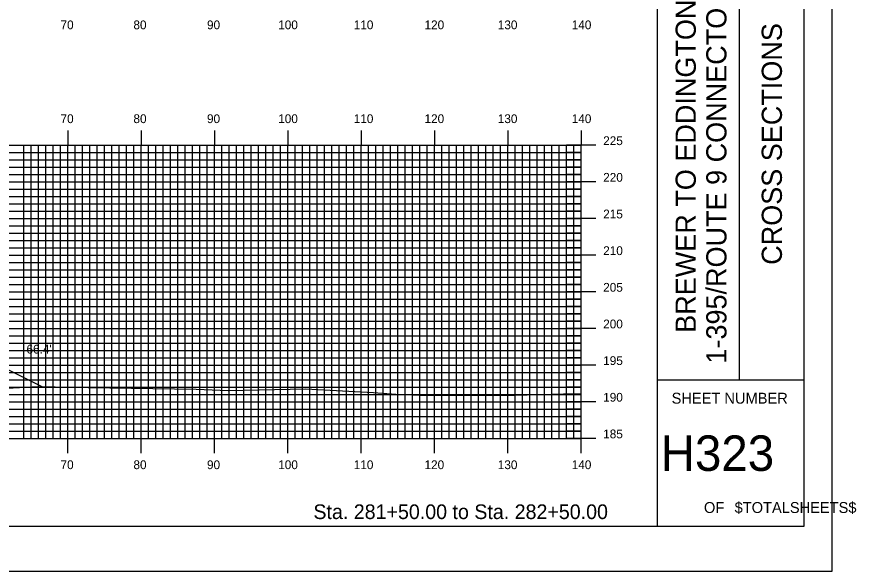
# Model space of a CAD drawing. Extents: x 1811374 to 1811717, y 442591 to 442811.
# Drawn here: x 1811602.4 to 1811716.9, y 442590.5 to 442666.2 of the extents above; entities that cross this region are included whole.
import ezdxf

# ---------------------------------------------------------------- set-up
doc = ezdxf.new("R2010")
doc.units = 0
for name, color, linetype in [('BORDER', 7, 'Continuous'), ('D_Roadway_Centerline', 7, 'Continuous'), ('D_Roadway_SlopeLines', 7, 'Continuous'), ('D_Text_Standard', 7, 'Continuous'), ('H_V ANNOTATION', 7, 'Continuous'), ('MAJOR', 7, 'Continuous'), ('MINOR', 7, 'Continuous'), ('PLOT BOUNDARY', 7, 'Continuous'), ('S_Roadway_Centerline', 7, 'Continuous')]:
    doc.layers.add(name, color=color, linetype=linetype)

msp = doc.modelspace()

# ---------------------------------------------------------------- linework, layer by layer
at = {"layer": 'BORDER'}
for p, q in [((1811689.8, 442596.67), (1811689.8, 442806.67)), ((1811700.98, 442616.67), (1811700.98, 442686.67)), ((1811689.8, 442616.67), (1811709.8, 442616.67))]:
    msp.add_line(p, q, dxfattribs=at)
msp.add_lwpolyline([(1811389.8, 442596.67), (1811709.8, 442596.67), (1811709.8, 442806.67), (1811389.8, 442806.67)], close=True, dxfattribs=at)
at = {"layer": 'D_Roadway_Centerline'}
msp.add_lwpolyline([(1811469.9, 442615.65), (1811511.19, 442636.3), (1811516.4, 442638.9), (1811519.4, 442638.96), (1811527.4, 442639.12), (1811539.4, 442638.54), (1811551.4, 442637.97), (1811559.4, 442637.58), (1811562.4, 442637.44), (1811567.93, 442634.68), (1811605.84, 442615.72)], dxfattribs=at)
at = {"layer": 'D_Roadway_SlopeLines'}
msp.add_lwpolyline([(1811562.4, 442637.44), (1811605.84, 442615.72)], dxfattribs=at)
at = {"layer": 'MAJOR'}
for p, q in [((1811609.4, 442650.67), (1811609.4, 442648.67)), ((1811619.4, 442650.67), (1811619.4, 442648.67)), ((1811629.4, 442650.67), (1811629.4, 442648.67)), ((1811639.4, 442650.67), (1811639.4, 442648.67)), ((1811649.4, 442650.67), (1811649.4, 442648.67)), ((1811659.4, 442650.67), (1811659.4, 442648.67)), ((1811669.4, 442650.67), (1811669.4, 442648.67)), ((1811679.4, 442650.67), (1811679.4, 442648.67)), ((1811399.4, 442648.67), (1811679.4, 442648.67)), ((1811399.4, 442648.67), (1811679.4, 442648.67)), ((1811609.4, 442608.67), (1811609.4, 442648.67)), ((1811619.4, 442608.67), (1811619.4, 442648.67)), ((1811629.4, 442608.67), (1811629.4, 442648.67)), ((1811639.4, 442608.67), (1811639.4, 442648.67)), ((1811649.4, 442608.67), (1811649.4, 442648.67)), ((1811659.4, 442608.67), (1811659.4, 442648.67)), ((1811669.4, 442608.67), (1811669.4, 442648.67)), ((1811681.41, 442648.67), (1811677.4, 442648.67)), ((1811679.4, 442608.67), (1811679.4, 442648.67)), ((1811679.4, 442608.67), (1811679.4, 442648.67)), ((1811399.4, 442643.67), (1811679.4, 442643.67)), ((1811681.41, 442643.67), (1811677.4, 442643.67)), ((1811399.4, 442638.67), (1811679.4, 442638.67)), ((1811681.41, 442638.67), (1811677.4, 442638.67)), ((1811399.4, 442633.67), (1811679.4, 442633.67)), ((1811681.41, 442633.67), (1811677.4, 442633.67)), ((1811399.4, 442628.67), (1811679.4, 442628.67)), ((1811681.41, 442628.67), (1811677.4, 442628.67)), ((1811399.4, 442623.67), (1811679.4, 442623.67)), ((1811681.41, 442623.67), (1811677.4, 442623.67)), ((1811399.4, 442618.67), (1811679.4, 442618.67)), ((1811681.41, 442618.67), (1811677.4, 442618.67)), ((1811399.4, 442613.67), (1811679.4, 442613.67)), ((1811681.41, 442613.67), (1811677.4, 442613.67)), ((1811399.4, 442608.67), (1811679.4, 442608.67)), ((1811399.4, 442608.67), (1811679.4, 442608.67)), ((1811609.4, 442606.66), (1811609.4, 442608.67)), ((1811619.4, 442606.66), (1811619.4, 442608.67)), ((1811629.4, 442606.66), (1811629.4, 442608.67)), ((1811639.4, 442606.66), (1811639.4, 442608.67)), ((1811649.4, 442606.66), (1811649.4, 442608.67)), ((1811659.4, 442606.66), (1811659.4, 442608.67)), ((1811669.4, 442606.66), (1811669.4, 442608.67)), ((1811681.41, 442608.67), (1811677.4, 442608.67)), ((1811679.4, 442606.66), (1811679.4, 442608.67))]:
    msp.add_line(p, q, dxfattribs=at)
at = {"layer": 'MINOR'}
for p, q in [((1811603.4, 442608.67), (1811603.4, 442648.67)), ((1811604.4, 442608.67), (1811604.4, 442648.67)), ((1811605.4, 442608.67), (1811605.4, 442648.67)), ((1811606.4, 442608.67), (1811606.4, 442648.67)), ((1811607.4, 442608.67), (1811607.4, 442648.67)), ((1811608.4, 442608.67), (1811608.4, 442648.67)), ((1811610.4, 442608.67), (1811610.4, 442648.67)), ((1811611.4, 442608.67), (1811611.4, 442648.67)), ((1811612.4, 442608.67), (1811612.4, 442648.67)), ((1811613.4, 442608.67), (1811613.4, 442648.67)), ((1811614.4, 442608.67), (1811614.4, 442648.67)), ((1811615.4, 442608.67), (1811615.4, 442648.67)), ((1811616.4, 442608.67), (1811616.4, 442648.67)), ((1811617.4, 442608.67), (1811617.4, 442648.67)), ((1811618.4, 442608.67), (1811618.4, 442648.67)), ((1811620.4, 442608.67), (1811620.4, 442648.67)), ((1811621.4, 442608.67), (1811621.4, 442648.67)), ((1811622.4, 442608.67), (1811622.4, 442648.67)), ((1811623.4, 442608.67), (1811623.4, 442648.67)), ((1811624.4, 442608.67), (1811624.4, 442648.67)), ((1811625.4, 442608.67), (1811625.4, 442648.67)), ((1811626.4, 442608.67), (1811626.4, 442648.67)), ((1811627.4, 442608.67), (1811627.4, 442648.67)), ((1811628.4, 442608.67), (1811628.4, 442648.67)), ((1811630.4, 442608.67), (1811630.4, 442648.67)), ((1811631.4, 442608.67), (1811631.4, 442648.67)), ((1811632.4, 442608.67), (1811632.4, 442648.67)), ((1811633.4, 442608.67), (1811633.4, 442648.67)), ((1811634.4, 442608.67), (1811634.4, 442648.67)), ((1811635.4, 442608.67), (1811635.4, 442648.67)), ((1811636.4, 442608.67), (1811636.4, 442648.67)), ((1811637.4, 442608.67), (1811637.4, 442648.67)), ((1811638.4, 442608.67), (1811638.4, 442648.67)), ((1811640.4, 442608.67), (1811640.4, 442648.67)), ((1811641.4, 442608.67), (1811641.4, 442648.67)), ((1811642.4, 442608.67), (1811642.4, 442648.67)), ((1811643.4, 442608.67), (1811643.4, 442648.67)), ((1811644.4, 442608.67), (1811644.4, 442648.67)), ((1811645.4, 442608.67), (1811645.4, 442648.67)), ((1811646.4, 442608.67), (1811646.4, 442648.67)), ((1811647.4, 442608.67), (1811647.4, 442648.67)), ((1811648.4, 442608.67), (1811648.4, 442648.67)), ((1811650.4, 442608.67), (1811650.4, 442648.67)), ((1811651.4, 442608.67), (1811651.4, 442648.67)), ((1811652.4, 442608.67), (1811652.4, 442648.67)), ((1811653.4, 442608.67), (1811653.4, 442648.67)), ((1811654.4, 442608.67), (1811654.4, 442648.67)), ((1811655.4, 442608.67), (1811655.4, 442648.67)), ((1811656.4, 442608.67), (1811656.4, 442648.67)), ((1811657.4, 442608.67), (1811657.4, 442648.67)), ((1811658.4, 442608.67), (1811658.4, 442648.67)), ((1811660.4, 442608.67), (1811660.4, 442648.67)), ((1811661.4, 442608.67), (1811661.4, 442648.67)), ((1811662.4, 442608.67), (1811662.4, 442648.67)), ((1811663.4, 442608.67), (1811663.4, 442648.67)), ((1811664.4, 442608.67), (1811664.4, 442648.67)), ((1811665.4, 442608.67), (1811665.4, 442648.67)), ((1811666.4, 442608.67), (1811666.4, 442648.67)), ((1811667.4, 442608.67), (1811667.4, 442648.67)), ((1811668.4, 442608.67), (1811668.4, 442648.67)), ((1811670.4, 442608.67), (1811670.4, 442648.67)), ((1811671.4, 442608.67), (1811671.4, 442648.67)), ((1811672.4, 442608.67), (1811672.4, 442648.67)), ((1811673.4, 442608.67), (1811673.4, 442648.67)), ((1811674.4, 442608.67), (1811674.4, 442648.67)), ((1811675.4, 442608.67), (1811675.4, 442648.67)), ((1811676.4, 442608.67), (1811676.4, 442648.67)), ((1811677.4, 442608.67), (1811677.4, 442648.67)), ((1811678.4, 442608.67), (1811678.4, 442648.67)), ((1811399.4, 442647.67), (1811679.4, 442647.67)), ((1811399.4, 442646.67), (1811679.4, 442646.67)), ((1811679.4, 442647.67), (1811677.4, 442647.67)), ((1811679.4, 442646.67), (1811677.4, 442646.67)), ((1811399.4, 442645.67), (1811679.4, 442645.67)), ((1811679.4, 442645.67), (1811677.4, 442645.67)), ((1811399.4, 442644.67), (1811679.4, 442644.67)), ((1811679.4, 442644.67), (1811677.4, 442644.67)), ((1811399.4, 442642.67), (1811679.4, 442642.67)), ((1811679.4, 442642.67), (1811677.4, 442642.67)), ((1811399.4, 442641.67), (1811679.4, 442641.67)), ((1811679.4, 442641.67), (1811677.4, 442641.67)), ((1811399.4, 442640.67), (1811679.4, 442640.67)), ((1811679.4, 442640.67), (1811677.4, 442640.67)), ((1811399.4, 442639.67), (1811679.4, 442639.67)), ((1811679.4, 442639.67), (1811677.4, 442639.67)), ((1811399.4, 442637.67), (1811679.4, 442637.67)), ((1811679.4, 442637.67), (1811677.4, 442637.67)), ((1811399.4, 442636.67), (1811679.4, 442636.67)), ((1811679.4, 442636.67), (1811677.4, 442636.67)), ((1811399.4, 442635.67), (1811679.4, 442635.67)), ((1811679.4, 442635.67), (1811677.4, 442635.67)), ((1811399.4, 442634.67), (1811679.4, 442634.67)), ((1811679.4, 442634.67), (1811677.4, 442634.67)), ((1811399.4, 442632.67), (1811679.4, 442632.67)), ((1811399.4, 442631.67), (1811679.4, 442631.67)), ((1811679.4, 442632.67), (1811677.4, 442632.67)), ((1811679.4, 442631.67), (1811677.4, 442631.67)), ((1811399.4, 442630.67), (1811679.4, 442630.67)), ((1811679.4, 442630.67), (1811677.4, 442630.67)), ((1811399.4, 442629.67), (1811679.4, 442629.67)), ((1811679.4, 442629.67), (1811677.4, 442629.67)), ((1811399.4, 442627.67), (1811679.4, 442627.67)), ((1811679.4, 442627.67), (1811677.4, 442627.67)), ((1811399.4, 442626.67), (1811679.4, 442626.67)), ((1811679.4, 442626.67), (1811677.4, 442626.67)), ((1811399.4, 442625.67), (1811679.4, 442625.67)), ((1811679.4, 442625.67), (1811677.4, 442625.67)), ((1811399.4, 442624.67), (1811679.4, 442624.67)), ((1811679.4, 442624.67), (1811677.4, 442624.67)), ((1811399.4, 442622.67), (1811679.4, 442622.67)), ((1811679.4, 442622.67), (1811677.4, 442622.67)), ((1811399.4, 442621.67), (1811679.4, 442621.67)), ((1811679.4, 442621.67), (1811677.4, 442621.67)), ((1811399.4, 442620.67), (1811679.4, 442620.67)), ((1811679.4, 442620.67), (1811677.4, 442620.67)), ((1811399.4, 442619.67), (1811679.4, 442619.67)), ((1811679.4, 442619.67), (1811677.4, 442619.67)), ((1811399.4, 442617.67), (1811679.4, 442617.67)), ((1811679.4, 442617.67), (1811677.4, 442617.67)), ((1811399.4, 442616.67), (1811679.4, 442616.67)), ((1811399.4, 442615.67), (1811679.4, 442615.67)), ((1811679.4, 442616.67), (1811677.4, 442616.67)), ((1811679.4, 442615.67), (1811677.4, 442615.67)), ((1811399.4, 442614.67), (1811679.4, 442614.67)), ((1811679.4, 442614.67), (1811677.4, 442614.67)), ((1811399.4, 442612.67), (1811679.4, 442612.67)), ((1811679.4, 442612.67), (1811677.4, 442612.67)), ((1811399.4, 442611.67), (1811679.4, 442611.67)), ((1811679.4, 442611.67), (1811677.4, 442611.67)), ((1811399.4, 442610.67), (1811679.4, 442610.67)), ((1811679.4, 442610.67), (1811677.4, 442610.67)), ((1811399.4, 442609.67), (1811679.4, 442609.67)), ((1811679.4, 442609.67), (1811677.4, 442609.67))]:
    msp.add_line(p, q, dxfattribs=at)
at = {"layer": 'PLOT BOUNDARY'}
msp.add_lwpolyline([(1811373.62, 442590.55), (1811713.62, 442590.55), (1811713.62, 442810.55), (1811373.62, 442810.55)], close=True, dxfattribs=at)
at = {"layer": 'S_Roadway_Centerline'}
msp.add_lwpolyline([(1811595.85, 442615.25), (1811605.4, 442615.73), (1811612.16, 442615.6), (1811626.89, 442615.37), (1811631.26, 442615.21), (1811641.83, 442615.44), (1811651.07, 442614.92), (1811654.11, 442614.7), (1811658.45, 442614.51), (1811670.41, 442614.55), (1811676.97, 442614.76), (1811679.4, 442614.75)], dxfattribs=at)

# ---------------------------------------------------------------- texts
at = {"layer": 'BORDER'}
for s, p in [('1-395/ROUTE 9 CONNECTOR', (1811699.21, 442618.87)), ('BREWER TO EDDINGTON', (1811695.03, 442623.07)), ('CROSS SECTIONS', (1811706.77, 442632.34))]:
    msp.add_text(s, height=2.7557, rotation=90, dxfattribs=at).set_placement(p)
for s, height, p in [('SHEET NUMBER', 1.4905, (1811691.73, 442613.4)), ('H323', 4.839, (1811690.24, 442604.23)), ('OF', 1.491, (1811696.14, 442598.49)), ('$TOTALSHEETS$', 1.4905, (1811700.32, 442598.49))]:
    msp.add_text(s, height=height, dxfattribs=at).set_placement(p)
at = {"layer": 'D_Text_Standard'}
msp.add_text("66.4'", height=1.2, dxfattribs=at).set_placement((1811603.77, 442620.24))
at = {"layer": 'H_V ANNOTATION'}
for s, height, p in [('70', 1.2, (1811608.41, 442664.47)), ('80', 1.2, (1811618.35, 442664.47)), ('90', 1.2, (1811628.38, 442664.47)), ('100', 1.2, (1811638.09, 442664.47)), ('110', 1.2, (1811648.39, 442664.47)), ('120', 1.2, (1811658.04, 442664.47)), ('130', 1.2, (1811668.03, 442664.47)), ('140', 1.2, (1811678.11, 442664.47)), ('70', 1.2, (1811608.41, 442651.67)), ('80', 1.2, (1811618.35, 442651.67)), ('90', 1.2, (1811628.38, 442651.67)), ('100', 1.2, (1811638.09, 442651.67)), ('110', 1.2, (1811648.39, 442651.67)), ('120', 1.2, (1811658.04, 442651.67)), ('130', 1.2, (1811668.03, 442651.67)), ('140', 1.2, (1811678.11, 442651.67)), ('225', 1.2, (1811682.4, 442648.67)), ('220', 1.2, (1811682.4, 442643.67)), ('215', 1.2, (1811682.4, 442638.67)), ('210', 1.2, (1811682.4, 442633.67)), ('205', 1.2, (1811682.4, 442628.67)), ('200', 1.2, (1811682.4, 442623.67)), ('195', 1.2, (1811682.4, 442618.67)), ('190', 1.2, (1811682.4, 442613.67)), ('185', 1.2, (1811682.4, 442608.67)), ('70', 1.2, (1811608.41, 442604.47)), ('80', 1.2, (1811618.35, 442604.47)), ('90', 1.2, (1811628.38, 442604.47)), ('100', 1.2, (1811638.09, 442604.47)), ('110', 1.2, (1811648.39, 442604.47)), ('120', 1.2, (1811658.04, 442604.47)), ('130', 1.2, (1811668.03, 442604.47)), ('140', 1.2, (1811678.11, 442604.47)), ('Sta. 281+50.00 to Sta. 282+50.00', 2.0004, (1811642.89, 442597.66))]:
    msp.add_text(s, height=height, dxfattribs=at).set_placement(p)

doc.saveas('drawing.dxf')
